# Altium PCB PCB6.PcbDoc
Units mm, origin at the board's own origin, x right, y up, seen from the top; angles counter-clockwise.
Board outline 32.77 x 33.4 mm, 2 copper layers (Top Layer, Bottom Layer); 18 components, 19 nets, 56 pads, 2 vias.
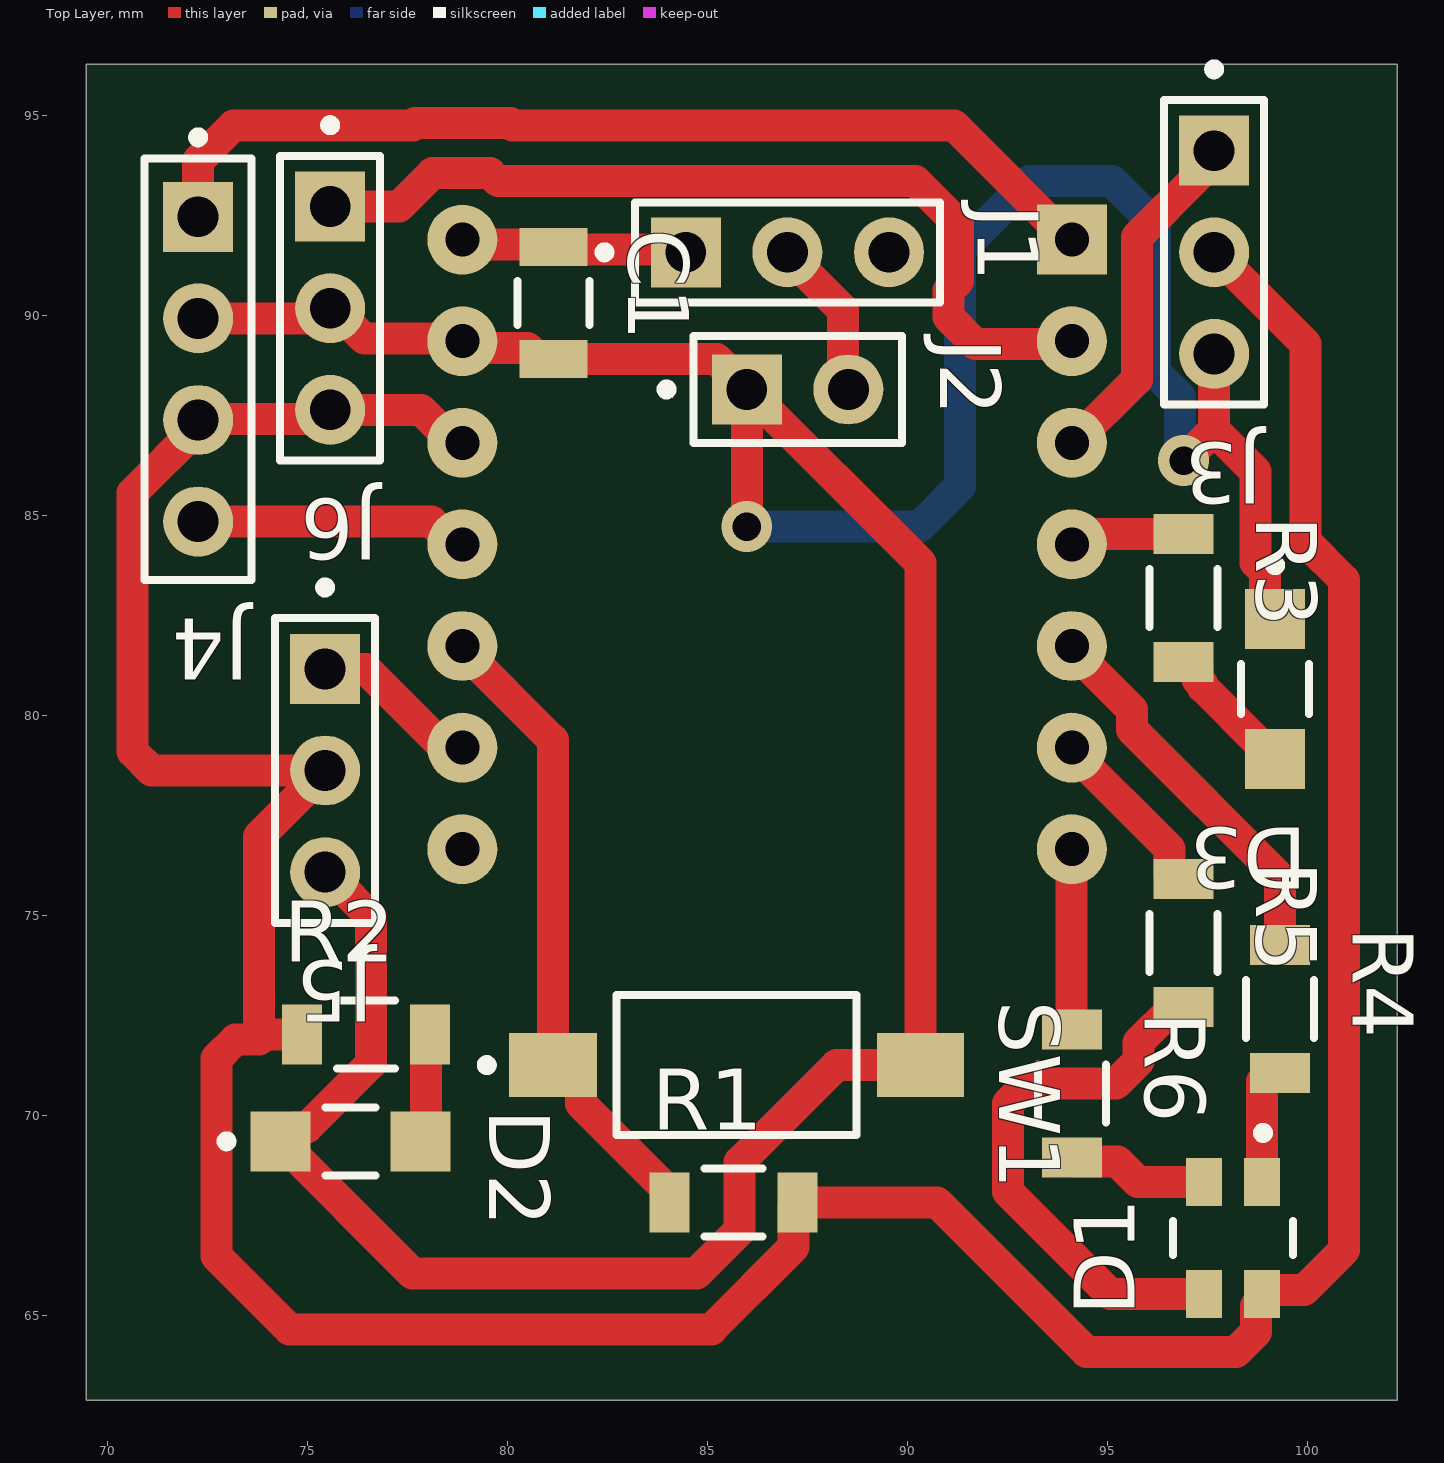
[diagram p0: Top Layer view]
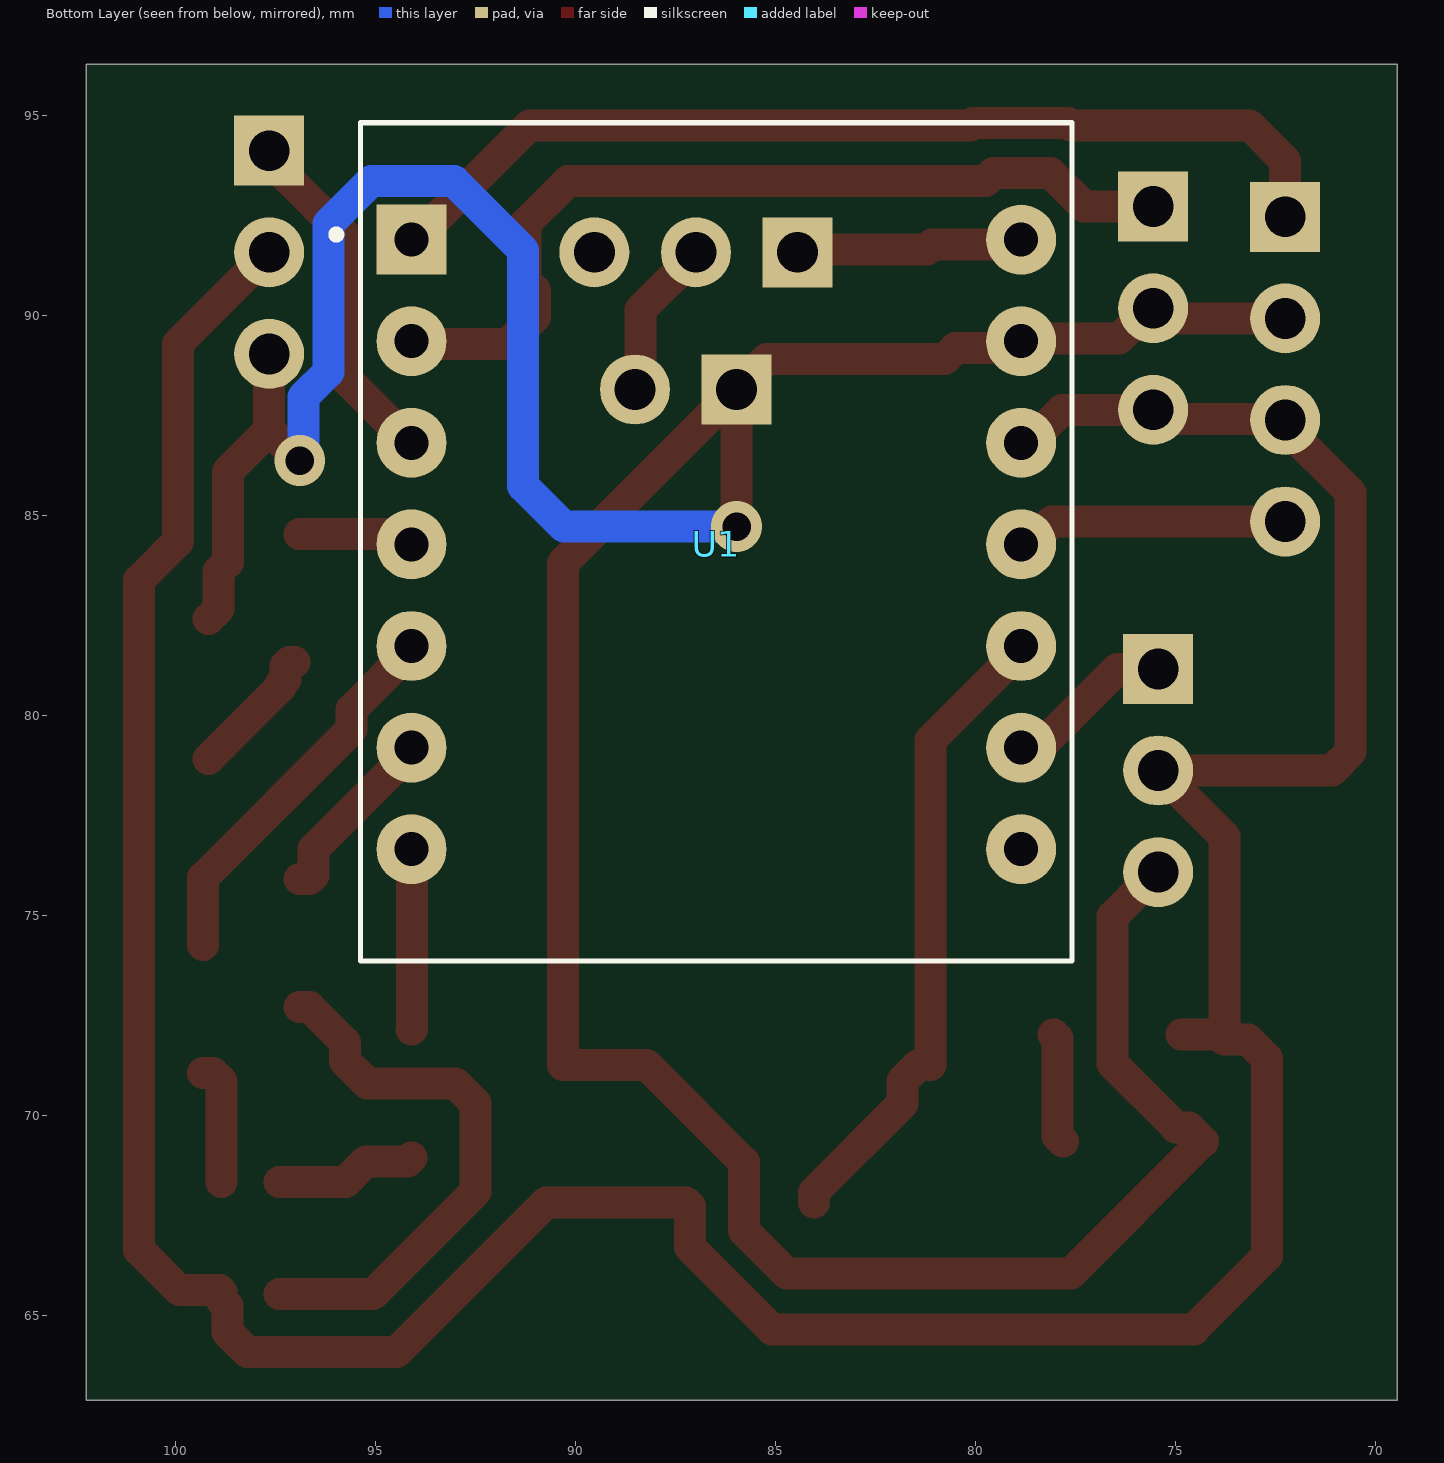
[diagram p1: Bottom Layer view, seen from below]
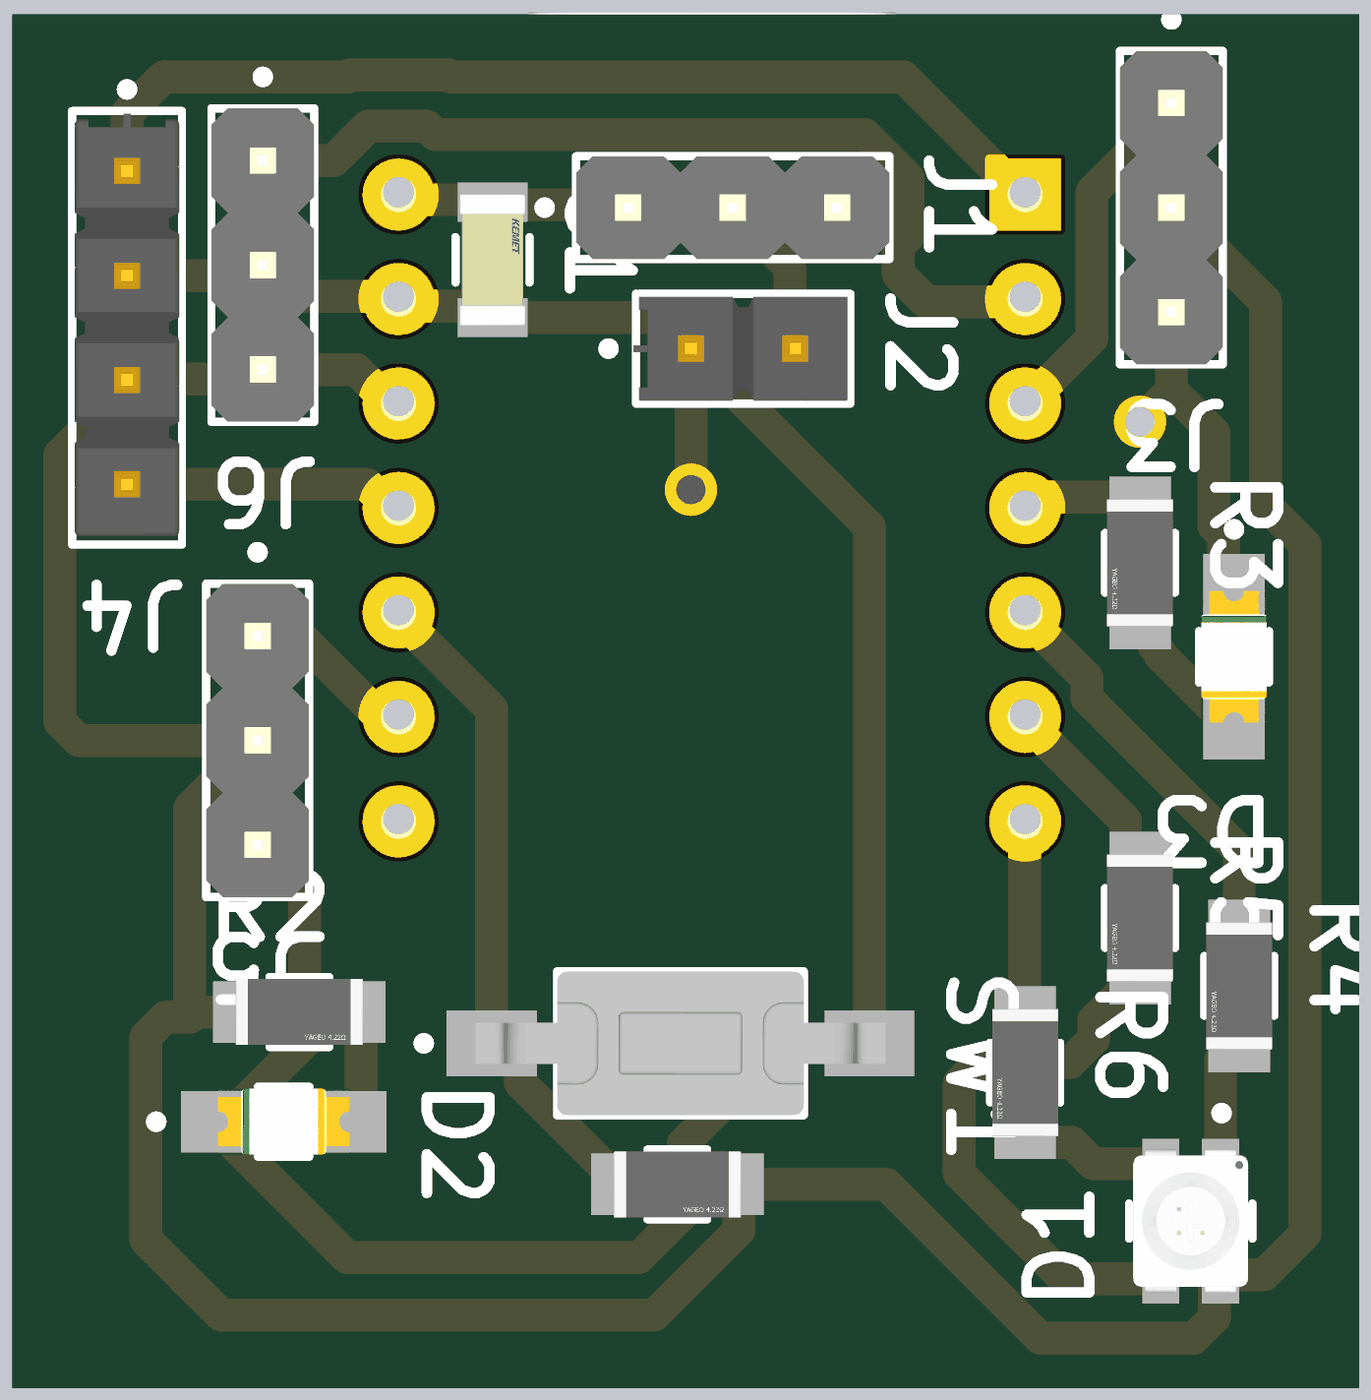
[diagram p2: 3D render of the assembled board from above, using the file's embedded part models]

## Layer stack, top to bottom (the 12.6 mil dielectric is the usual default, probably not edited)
Top Solder: solder mask 0.0102, Solder Resist, Dk 3.5
Top Layer: signal copper 0.0356
Dielectric 1: dielectric 0.32, FR-4, Dk 4.8
Bottom Layer: signal copper 0.0356
Bottom Solder: solder mask 0.0102, Solder Resist, Dk 3.5

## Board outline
69.469,62.865 69.469,96.266 102.235,96.266 102.235,62.865

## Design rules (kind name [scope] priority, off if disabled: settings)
Clearance [All] p1: gap=0.45 ignorepadtopadclearanceinfootprint=FALSE
PolygonConnect [All] p1: connectstyle=Relief reliefconductorwidth=0.254 reliefentries=4 polygonreliefangle="90 Angle" airgapwidth=0.254
RoutingVias [All] p1: holewidth=0.711 width=1.27 viastyle="Through Hole" minholewidth=0.711 minwidth=1.27 maxholewidth=0.711 maxwidth=1.27
SolderMaskExpansion [All] p1: expansion=0 istentingtop=FALSE
SupplyNets "Schematic Supply Nets_1" [InNet('GND')] p1: voltage=0.000
SupplyNets "Schematic Supply Nets" [InNet('VCC')] p2: voltage=0.000
Width [All] p1: maxlimit=0.8 minlimit=0.8 preferedwidth=0.8 minimp=50.000000 maximp=50.000000 favimp=50.000000
30 further rules are at their usual default settings.

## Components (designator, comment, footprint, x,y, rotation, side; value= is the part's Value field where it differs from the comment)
C1 "." FP-C1206C-EB-MFG 81.153,90.297 r270 top value="100 pF"
D1 "LED RGB" FP-AAA3528LSEKJ3ZGKQBKS-MFG 98.134,66.926 r90 top
D2 "LED" FP-LTST-C150KSKT-MFG 76.073,69.342 r0 top
D3 "LED_2" FP-LTST-C150KSKT-MFG 99.187,80.645 r270 top
J1 "SWITCH" FP-PR20203VBNN-MFG 86.995,91.567 r0 top
J2 "POWER" FP-TSW-102-12-T-S-MFG 87.249,88.138 r0 top
J3 "MOTOR1" FP-PR20203VBNN-MFG 97.663,91.567 r270 top
J4 "MICRO1" FP-TSW-104-22-G-S-MFG 72.263,88.646 r270 top
J5 "MOTOR2" FP-PR20203VBNN-MFG 75.438,78.613 r270 top
J6 "MICRO2" FP-PR20203VBNN-MFG 75.565,90.17 r270 top
R1 "." FP-AC1206-MFG 85.649,67.818 r0 top value=2.21KΩ
R2 "." FP-AC1206-MFG 76.454,72.009 r0 top value=2.21KΩ
R3 "." FP-AC1206-MFG 96.901,82.931 r270 top value=2.21KΩ
R4 "." FP-AC1206-MFG 99.314,72.644 r270 top value=2.21KΩ
R5 "." FP-AC1206-MFG 96.901,74.295 r270 top value=2.21KΩ
R6 "." FP-AC1206-MFG 94.107,70.536 r270 top value=2.21KΩ
SW1 "BUTTON" TECO-FSMSM-2_V 85.725,71.247 r0 top
U1 "XIAO_ESP32C3" MODULE_XIAO_ESP32C3 86.487,84.328 r180 bottom

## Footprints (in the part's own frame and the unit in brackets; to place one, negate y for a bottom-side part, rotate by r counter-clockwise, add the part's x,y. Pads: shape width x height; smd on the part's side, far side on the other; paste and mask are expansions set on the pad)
FP-AAA3528LSEKJ3ZGKQBKS-MFG [mm]
  rect 1.2x0.9 smd paste+0 mask+0: 1(1.4,-0.725) 2(-1.4,-0.725) 3(-1.4,0.725) 4(1.4,0.725)
  silkscreen extent -0.43,-1.5 2.75,1.5, body extent -2.1,-1.6 2.1,1.6, height 0.25
FP-AC1206-MFG [mm]
  rect 1x1.5 smd paste+0 mask+0: 1(-1.6,0) 2(1.6,0)
  silkscreen extent -0.72,-0.85 0.72,0.85, body extent -2.2,-0.95 2.2,0.95, height 0.25
FP-C1206C-EB-MFG [mm]
  rect 0.95x1.7 smd paste+0 mask+0: 1(-1.4,0) 2(1.4,0)
  silkscreen extent -0.55,-0.9 0.55,0.9, body extent -2,-1 2,1, height 0.25
FP-LTST-C150KSKT-MFG [mm]
  rect 1.5x1.5 smd paste+0 mask+0: 1(-1.75,0) 2(1.75,0)
  silkscreen extent -3.22,-0.85 0.63,0.85, body extent -2.6,-0.95 2.6,0.95, height 0.25
FP-PR20203VBNN-MFG [mm]
  rect 1.75x1.75 hole 1.02 paste-2539.97 mask+0: 1(-2.54,0)
  round 1.75 hole 1.02 paste-2539.97 mask+0: 2(0,0) 3(2.54,0)
  silkscreen extent -4.7,-1.25 3.81,1.25, body extent -3.91,-1.35 3.91,1.35, height 0.25
FP-TSW-102-12-T-S-MFG [mm]
  rect 1.75x1.75 hole 1.02 paste-2539.97 mask+0: 1(-1.27,0)
  round 1.75 hole 1.02 paste-2539.97 mask+0: 2(1.27,0)
  silkscreen extent -3.4,-1.34 2.61,1.34, body extent -2.71,-1.44 2.71,1.44, height 0.25
FP-TSW-104-22-G-S-MFG [mm]
  rect 1.75x1.75 hole 1.02 paste-2539.97 mask+0: 1(-3.81,0)
  round 1.75 hole 1.02 paste-2539.97 mask+0: 2(-1.27,0) 3(1.27,0) 4(3.81,0)
  silkscreen extent -5.92,-1.34 5.27,1.34, body extent -5.37,-1.44 5.37,1.44, height 0.25
MODULE_XIAO_ESP32C3 [mm]
  rect 1.75x1.75 hole 0.85 mask+0.102: 1(-7.62,7.557)
  round 1.75 hole 0.85 mask+0.102: 2(-7.62,5.017) 3(-7.62,2.477) 4(-7.62,-0.063) 5(-7.62,-2.603) 6(-7.62,-5.143) 7(-7.62,-7.683) 8(7.62,-7.684) 9(7.62,-5.144) 10(7.62,-2.604) 11(7.62,-0.064) 12(7.62,2.476) 13(7.62,5.016) 14(7.62,7.556)
  silkscreen extent -9.6,-10.48 8.89,10.48, body extent -8.89,-10.48 8.89,11.99, height 4.21
TECO-FSMSM-2_V [mm] "SMD, 2-Leads, Body 6x3.5mm, Pitch 9.19mm"
  rect 2.2x1.6 smd: 1(-4.595,0)
  rect 2.18x1.6 smd: 2(4.595,0)
  silkscreen extent -6.37,-1.75 3,1.75, body extent -4.98,-1.75 4.98,1.75, height 4.4

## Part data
C1: library part CMP-03020-023751-1, "C1206 100 pF X8R 10.00% 50 V", Capacitance="100 pF", Manufacturer=KEMET, Manufacturer Part Number=C1206C101K5HACTU, Package=C1206C-EB, Temperature="-55°C to +150°C", Temperature Characteristic=X8R, Temperature Coefficient=15%, Temperature Range High=+150°C, Temperature Range Low=-55°C, Tolerance=0.1, Voltage Rating="50 V"
D1: library part CMP-44529-000057-1, "LED RGB CLEAR 4SMD", Case/Package=PLCC, Color=Blue, Forward Voltage=2.7V, Lens Color=Colorless, Test Current=2mA
D2 D3: library part CMP-2000-06618-2, "LED YELLOW CLEAR 1206 SMD", Case Code (Imperial)=1206, Case Code (Metric)=3216, Color=Yellow, Forward Current=30mA, Forward Voltage=2.4V, Lens Color=Colorless, Max Operating Temperature=85°C, Min Operating Temperature=-55°C, Package Quantity=1, Power Dissipation=75mW, Reverse Voltage=5V, Test Current=20mA
J1 J3 J5 J6: library part CMP-77940-000002-1, "CONN HEADER VERT 3POS 2.54MM", Current Rating=3A, Manufacturer="Metz Connect", Manufacturer Part Number=PR20203VBNN, Temperature="-40°C to +105°C", Temperature Range High=+105°C, Temperature Range Low=-40°C
J2: library part CMP-02766-001444-1, "CONN HEADER VERT 2POS 2.54MM"
J4: library part CMP-02766-001236-1, "CONN HEADER VERT 4POS 2.54MM"
R1 R2 R3 R4 R5 R6: library part CMP-03412-032679-1, "RES SMD 2.21K OHM 1% 1/4W 1206", Manufacturer=Yageo, Manufacturer Part Number=AC1206FR-072K21L, Package=AC1206, Power Rating=0.25W, Resistance=2.21KΩ, Temperature="-55°C to +155°C", Temperature Range High=+155°C, Temperature Range Low=-55°C, Tolerance=0.01, Voltage Rating=200V
SW1: library part CMP-2000-07511-1, "FSMSM Push Button Switch, 50 mA, -35 to 85 degC, 2-Pin SMD, RoHS, Bulk", Case\/Package=SMD/SMT, Contact Current Rating=50mA, Contact Resistance=100mOhm, Manufacturer="TE Connectivity", Max Operating Temperature=85degC, Max Voltage Rating (DC)=12V, Min Operating Temperature=-35degC, Operating Force=180gf, Package Description="2-Pin Surface Mount Device, Body 6 x 3.5 mm, Pitch 9.19 mm", Package Quantity=1000, Package Reference=FSMSM, Voltage Rating (DC)=24V
U1: "Dev.kit: evaluation; u.FL antenna,prototype board; XIAO; PIN: 2x7", Package=None

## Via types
v1: diameter 1.27, hole 0.711, Top Layer to Bottom Layer, 2 vias

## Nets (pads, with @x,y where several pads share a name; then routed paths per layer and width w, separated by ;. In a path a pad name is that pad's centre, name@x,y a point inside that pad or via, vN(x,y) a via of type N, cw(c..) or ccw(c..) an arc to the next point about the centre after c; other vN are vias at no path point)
3V3: D1.2 J3.2 J4.3 J5.2 J6.3 R1.2 R2.1 U1.12 | length 95.8
  Top Layer w0.8: J4.3@72.263,87.399 J4.3 72.263,87.191 70.628,85.556 70.628,79.082 71.097,78.613 J5.2 73.787,76.962 73.787,72.136 73.914,72.009 R2.1 ; J4.3@72.286,87.399 75.126,87.399 75.357,87.63 J6.3 77.838,87.63 78.727,86.741 U1.12@78.84,86.741 ; 73.787,71.882 73.192,71.882 72.723,71.413 72.723,66.469 74.549,64.643 85.094,64.643 87.149,66.698 87.149,67.718 R1.2 90.734,67.818 94.476,64.076 98.211,64.076 98.709,64.574 98.709,65.226 98.859,65.376 D1.2 98.859,65.571 98.909,65.621 99.911,65.621 100.914,66.624 100.914,83.37 99.949,84.335 99.949,89.281 J3.2
5V: C1.1 J1.1 U1.14 | length 5.7
  Top Layer w0.8: U1.14@78.84,91.821 78.902,91.759 81.091,91.759 C1.1 81.218,91.632 84.39,91.632 J1.1
A0: J4.1 U1.1 | length 24.8
  Top Layer w0.8: J4.1 72.263,93.853 73.152,94.742 77.635,94.742 77.689,94.796 80.072,94.796 80.126,94.742 91.159,94.742 U1.1@94.08,91.821
A1: J6.1 U1.2 | length 22.5
  Top Layer w0.8: J6.1@75.401,92.71 77.289,92.71 78.125,93.546 79.555,93.546 79.756,93.345 90.197,93.345 91.26,92.282 91.26,90.852 91.023,90.615 91.023,89.952 91.694,89.281 U1.2@94.08,89.281
D2: J3.1 U1.3 | length 8.9
  Top Layer w0.8: U1.3@94.08,86.741 95.732,88.393 95.732,91.949 97.278,93.494 97.278,93.722 J3.1
D3: R3.1 U1.4 | length 3
  Top Layer w0.8: U1.4@94.08,84.201 94.231,84.201 94.561,84.531 R3.1
D4: R4.1 U1.5 | length 9.6
  Top Layer w0.8: U1.5@94.08,81.661 95.609,80.132 95.609,79.639 99.314,75.934 R4.1
D5: R5.1 U1.6 | length 4.5
  Top Layer w0.8: U1.6@94.08,79.121 96.551,76.65 96.551,75.995 96.651,75.895 R5.1
D6: R6.1 U1.7 | length 4.5
  Top Layer w0.8: U1.7@94.08,76.581 94.093,76.567 94.093,72.15 R6.1
D8: J5.1 U1.9 | length 4.2
  Top Layer w0.8: J5.1 76.454,81.153 78.379,79.228 78.733,79.228 U1.9@78.84,79.121
D9: R1.1 SW1.1 U1.10 | length 15.9
  Top Layer w0.8: U1.10@78.84,81.661 81.13,79.371 SW1.1 ; SW1.1@81.43,71.247 81.83,70.847 81.83,70.287 84.049,68.068 R1.1
D10: J4.4 U1.11 | length 7.1
  Top Layer w0.8: J4.4@72.008,84.836 78.092,84.836 78.727,84.201 U1.11@78.84,84.201
GND: C1.2 D2.1 D3.1 J2.1 J3.3 J4.2 J5.3 J6.2 SW1.2 U1.13 | length 97.5
  Top Layer w0.8: J4.2@72.471,89.916 75.103,89.916 75.357,90.17 J6.2 75.657,90.17 76.419,89.408 78.562,89.408 78.796,89.174 80.501,89.174 80.778,88.897 C1.2 85.22,88.897 J2.1 ; J5.3@75.712,76.073 75.704,76.065 75.704,75.836 76.581,74.959 76.581,71.284 74.989,69.692 74.673,69.692 D2.1 77.625,66.04 84.723,66.04 85.798,67.115 85.798,68.819 88.226,71.247 SW1.2 90.32,83.797 J2.1 ; v1(85.979,84.709) J2.1 ; v1(96.901,86.36) 97.663,87.122 ; J3.3 97.663,87.122 ; D3.1 98.933,82.649 98.933,83.583 98.699,83.817 98.699,86.086 97.663,87.122
  Bottom Layer w0.8: v1(85.979,84.709) 90.297,84.709 91.313,85.725 91.313,91.614 93.049,93.35 95.111,93.35 96.188,92.273 96.188,88.571 96.811,87.948 96.811,86.45 v1(96.901,86.36)
NetD1_1: D1.1 R4.2 | length 3.1
  Top Layer w0.8: D1.1 98.859,70.839 99.064,71.044 R4.2
NetD1_3: D1.3 R5.2 | length 13.8
  Top Layer w0.8: R5.2 96.651,72.695 95.775,71.819 95.775,71.352 95.209,70.786 93.005,70.786 92.507,70.288 92.507,68.084 95.065,65.526 D1.3
NetD1_4: D1.4 R6.2 | length 3.6
  Top Layer w0.8: R6.2 94.207,68.836 95.249,68.836 95.759,68.326 D1.4
NetD2_2: D2.2 R2.2 | length 2.8
  Top Layer w0.8: D2.2 77.954,69.473 77.954,71.909 R2.2
NetD3_2: D3.2 R3.2 | length 3.4
  Top Layer w0.8: R3.2@97.028,81.331 97.151,81.331 97.251,81.231 97.251,80.889 97.378,80.762 97.378,80.704 98.837,79.245 D3.2
VCC: J1.2 J2.2 | length 4.1
  Top Layer w0.8: J1.2 86.995,91.513 88.385,90.123 88.385,88.272 J2.2
pads on no net: J1.3 U1.8

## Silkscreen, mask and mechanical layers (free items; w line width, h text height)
Mechanical 1:
  the board outline again, w1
